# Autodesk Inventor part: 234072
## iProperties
Created: 2006-08
Part Number: 234072
Material: 8.8 vz
Description: Sechskantschraube
Vendor: Autodesk Inc.
Document SubType Name: Modeling
Standard: DIN 933
Designer: I.Baliuc
Standards Organization: DIN
Language: de-DE
Size Designation: M6 x 25
Categories: <MemberInstance Version="R10.0.0"><Categories><Category DisplayName="Schrauben" InternalName="e4da775c-781d-43d5-af7c-5136215cf5a6" Mnemonic="FSTN"><Category Di
Density: 7.85 g/cm^3
Abmessung: M6 x 25
Author: T.Messerschmitt
Comments: DIN 933 - M6 x 25
Revision Number: 234072
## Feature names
1. Körper [Revolution]
2. Kopf [Extrusion]
3. Fase1 [Revolution]
4. Fase2 [Chamfer]
